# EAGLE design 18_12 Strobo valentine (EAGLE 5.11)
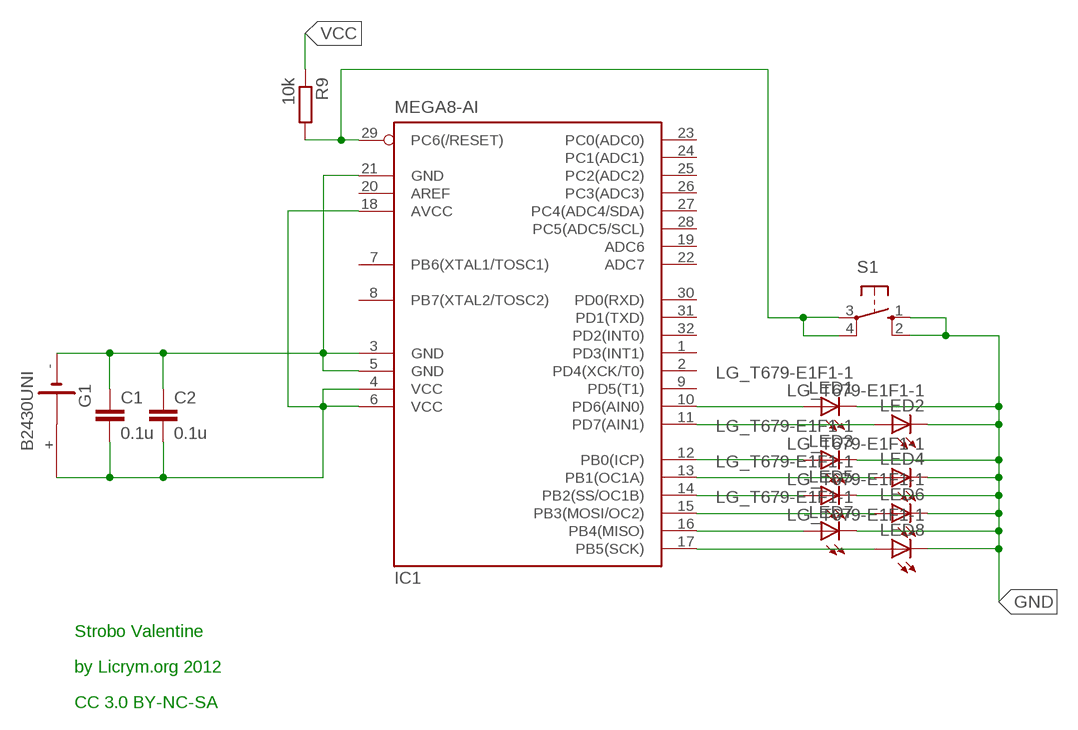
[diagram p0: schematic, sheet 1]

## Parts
C1  0.1u  C-EUC1206  [C1206]
C2  0.1u  C-EUC1206  [C1206]
G1  B2430UNI  [B2430UNI]
IC1  MEGA8-AI  [TQFP32-08]
LED1  LG_T679-E1F1-1  [PLCC2]
LED2  LG_T679-E1F1-1  [PLCC2]
LED3  LG_T679-E1F1-1  [PLCC2]
LED4  LG_T679-E1F1-1  [PLCC2]
LED5  LG_T679-E1F1-1  [PLCC2]
LED6  LG_T679-E1F1-1  [PLCC2]
LED7  LG_T679-E1F1-1  [PLCC2]
LED8  LG_T679-E1F1-1  [PLCC2]
R9  10k  R-EU_M1206  [M1206]
S1  10-XX  [B3F-10XX]

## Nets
GND: C1.1 C2.1 G1.- IC1.3(GND) IC1.5(GND) IC1.21(GND) LED1.C LED2.C LED3.C LED4.C LED5.C LED6.C LED7.C LED8.C S1.1(S) S1.2(S1)
N$3: IC1.29(PC6(/RESET)) R9.2 S1.3(P) S1.4(P1)
N$4: IC1.10(PD6(AIN0)) LED1.A
N$5: IC1.11(PD7(AIN1)) LED2.A
N$7: IC1.13(PB1(OC1A)) LED4.A
N$8: IC1.14(PB2(SS/OC1B)) LED5.A
N$9: IC1.15(PB3(MOSI/OC2)) LED6.A
N$10: IC1.16(PB4(MISO)) LED7.A
N$11: IC1.17(PB5(SCK)) LED8.A
N$14: IC1.12(PB0(ICP)) LED3.A
VCC: C1.2 C2.2 G1.+ IC1.4(VCC) IC1.6(VCC) IC1.18(AVCC) R9.1
Unconnected: G1.+@1(+) G1.+@2(+) G1.+@3(+) G1.+@4(+) G1.-@1(-) IC1.1(PD3(INT1)) IC1.2(PD4(XCK/T0)) IC1.7(PB6(XTAL1/TOSC1)) IC1.8(PB7(XTAL2/TOSC2)) IC1.9(PD5(T1)) IC1.19(ADC6) IC1.20(AREF) IC1.22(ADC7) IC1.23(PC0(ADC0)) IC1.24(PC1(ADC1)) IC1.25(PC2(ADC2)) IC1.26(PC3(ADC3)) IC1.27(PC4(ADC4/SDA)) IC1.28(PC5(ADC5/SCL)) IC1.30(PD0(RXD)) IC1.31(PD1(TXD)) IC1.32(PD2(INT0))

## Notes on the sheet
- Strobo Valentine
- by Licrym.org 2012
- CC 3.0 BY-NC-SA

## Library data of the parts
C1 C2 = rcl:C-EU: CAPACITOR, European symbol
G1 = battery:B2430UNI: LI BATTERY
IC1 = atmel:MEGA8: MICROCONTROLLER 8 Kbytes FLASH, 1 kbytes SRAM, 512 bytes EEPROM, USART, 6-channel 10 bit ADC, 2-channel 8 bit ADC Pin compatible with Atmega48, ATMega88, ATMega168 Source: avr.lbr; MPN: ATMEGA8-16AU; OC_FARNELL: 9171371; OC_NEWARK: 73M8863
LED1-LED8 = led:*_T679-?-1: LC TOPLED® Low Current LED; COLOR: green
R9 = rcl:R-EU_: RESISTOR, European symbol
S1 = switch-omron:10-XX: OMRON SWITCH; MPN: B3F-1000; OC_FARNELL: 176432; OC_NEWARK: 36M3542

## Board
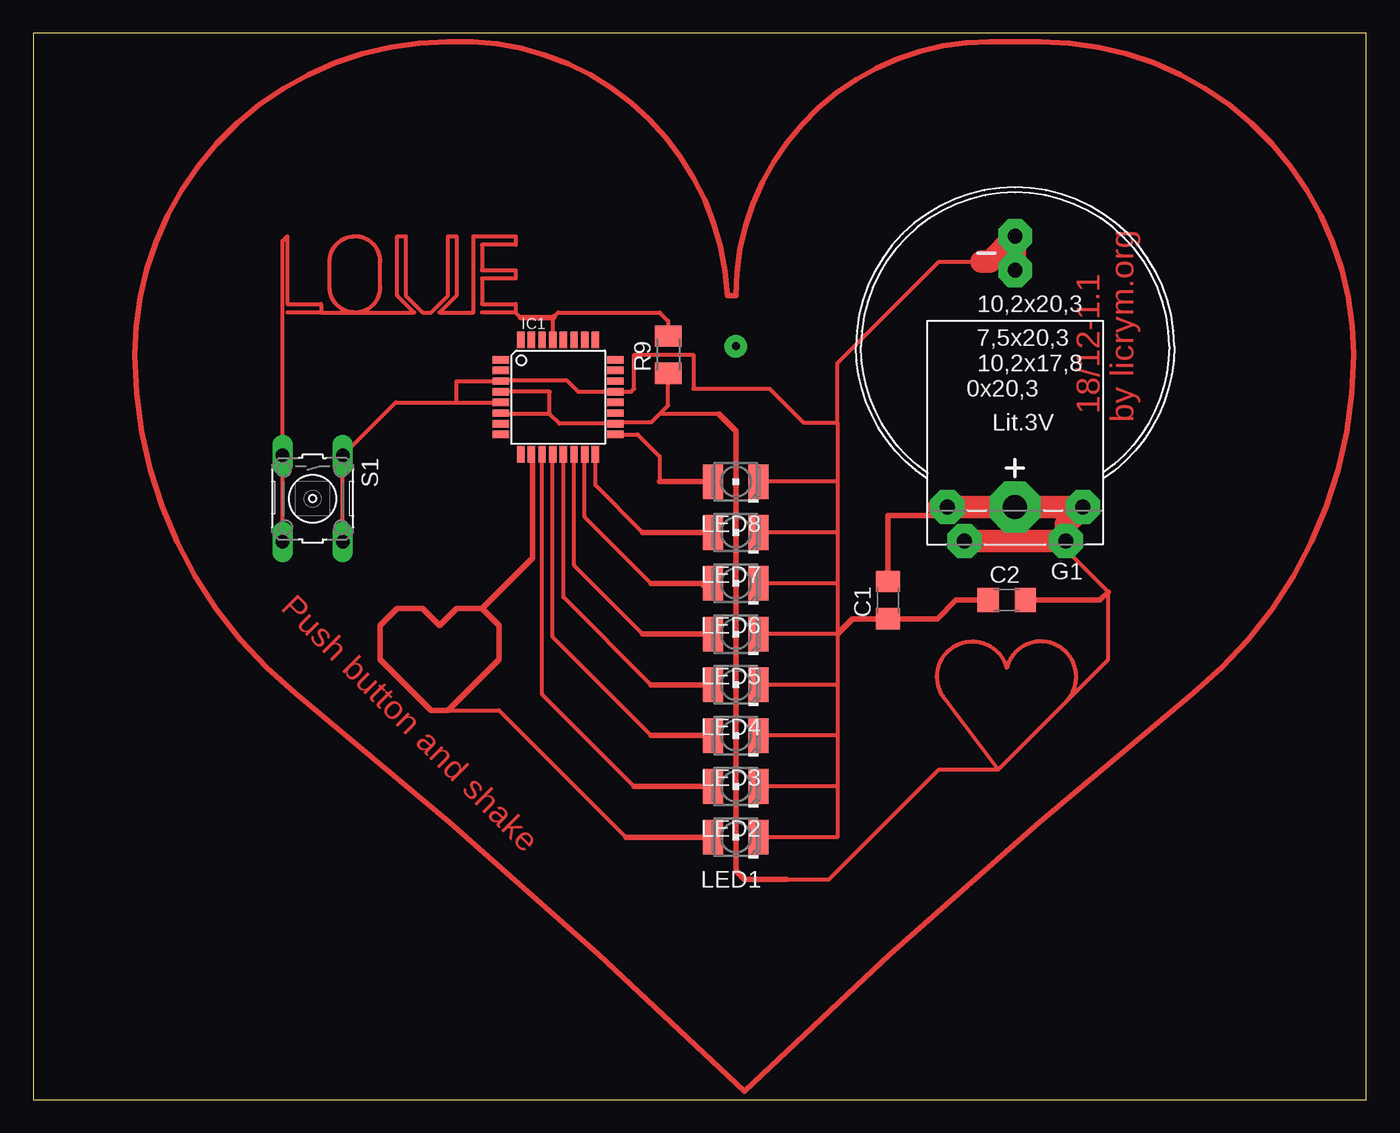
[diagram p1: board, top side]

Size 100 x 80 mm. Coordinates in mm from the lower left corner, seen from the top.
Outline: 0,0 100,0 100,80 0,80 0,0
Copper layers (1*16): Top 0.035mm / dielectric 1.5mm / Bottom 0.035mm
Design rules "default": minimum track width 10mil, minimum drill 24mil, track to track 8mil, track to pad 8mil, pad to pad 8mil, via to via 8mil, smd to smd 8mil, copper to edge 40mil, drill to drill 8mil, minimum pad ring 10mil, minimum via ring 8mil, stop-mask expansion 4mil, vias tented up to drill 0mil, thermal gap 10mil

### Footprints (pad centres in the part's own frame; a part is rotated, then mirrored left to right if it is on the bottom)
C1206 = smd 1.6 x 1.8: 1 -1.4,0; 2 1.4,0
B2430UNI = drill 1.118 pad 2.54 octagon: + 3.81,14.605; +@1 -3.81,14.605; +@2 -5.08,12.065; +@3 5.08,12.065; - 0,-5.715; -@1 0,-8.255 | drill 1.803 pad 3.81 octagon: +@4 0,12.065
TQFP32-08 = smd 1.27 x 0.559: 1 -4.293,2.8; 2 -4.293,2; 3 -4.293,1.2; 4 -4.293,0.4; 5 -4.293,-0.4; 6 -4.293,-1.2; 7 -4.293,-2; 8 -4.293,-2.8; 17 4.293,-2.8; 18 4.293,-2; 19 4.293,-1.2; 20 4.293,-0.4; 21 4.293,0.4; 22 4.293,1.2; 23 4.293,2; 24 4.293,2.8 | smd 0.559 x 1.27: 9 -2.8,-4.293; 10 -2,-4.293; 11 -1.2,-4.293; 12 -0.4,-4.293; 13 0.4,-4.293; 14 1.2,-4.293; 15 2,-4.293; 16 2.8,-4.293; 25 2.8,4.293; 26 2,4.293; 27 1.2,4.293; 28 0.4,4.293; 29 -0.4,4.293; 30 -1.2,4.293; 31 -2,4.293; 32 -2.8,4.293
PLCC2 = smd 2.6 x 1.5: A 0,1.7; C 0,-1.7
M1206 = smd 1.6 x 2: 1 -1.4,0; 2 1.4,0
B3F-10XX = drill 1.016 long: 1 -3.251,2.261; 2 3.251,2.261; 3 -3.251,-2.261; 4 3.251,-2.261

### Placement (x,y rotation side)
C1  64.14,37.47 90 top
C2  73.03,37.47 0 top
G1  73.66,56.52 180 top
IC1  39.37,52.7 0 top
LED1  52.7,19.68 90 top
LED2  52.7,23.5 90 top
LED3  52.7,27.3 90 top
LED4  52.7,31.11 90 top
LED5  52.7,34.92 90 top
LED6  52.7,38.73 90 top
LED7  52.7,42.55 90 top
LED8  52.7,46.35 90 top
R9  47.62,55.88 90 top
S1  20.95,45.09 270 top

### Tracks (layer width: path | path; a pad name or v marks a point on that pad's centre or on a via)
GND
  Top 0.305: S1.2 S1.1 27.18,52.3 31.75,52.3 | 31.75,52.3 IC1.5 | 31.75,52.3 31.75,53.91 IC1.3 35.15,53.98 40.01,53.98 40.88,53.1 IC1.21 44.85,53.1 45.09,53.34 45.09,55.88 49.53,55.88 49.53,53.34 55.24,53.34 57.78,50.8 60.33,50.8 | LED1.C 60.33,19.68 60.33,23.5 | 60.33,27.3 60.33,23.5 | 60.33,31.11 60.33,27.3 | 60.33,34.92 60.33,31.11 | 60.33,38.73 60.33,34.92 | 60.33,42.55 60.33,38.73 | 60.33,46.35 60.33,42.55 | 60.33,46.35 LED8.C | 60.33,42.55 LED7.C | 60.33,38.73 LED6.C | 60.33,34.92 LED5.C | 60.33,31.11 LED4.C | 60.33,27.3 LED3.C | 60.33,23.5 LED2.C | 60.33,50.8 60.33,46.35 | 60.33,50.8 60.33,55.24 67.94,62.87 71.12,62.87
  Top 0.406: 60.33,34.92 61.47,36.06 C1.1 67.81,36.06 69.22,37.47 C2.1
  Top 1.676: 71.12,62.87 71.75,62.87 73.66,64.77 G1.-
N$2
  Top 0.406: 31.11,79.38 arc90 7.62,55.88 arc51 19.68,30.48 arc-5 53.34,0.64
N$3
  Top 0.305: IC1.29 38.97,58.66 39.05,58.74 39.37,59.05 46.99,59.05 47.62,58.42 R9.2 | S1.4 S1.3 18.69,64.41 19.05,64.77 19.05,59.69 21.59,59.69 21.59,59.05 | 21.59,59.05 19.05,59.05 | 21.59,59.05 24.13,59.05 | 24.13,59.05 arc-90 22.23,60.96 22.23,62.87 arc-90 24.13,64.77 arc-90 26.04,62.87 26.04,60.96 arc-90 24.13,59.05 | 24.13,59.05 28.57,59.05 27.3,60.33 27.3,64.77 27.94,64.77 27.94,60.33 29.21,59.05 29.84,59.05 31.11,60.33 31.11,64.77 31.75,64.77 31.75,60.33 30.48,59.05 33.02,59.05 33.02,64.77 36.2,64.77 36.2,64.14 33.66,64.14 33.66,62.23 36.2,62.23 36.2,61.59 33.66,61.59 33.66,59.69 36.2,59.69 36.2,59.05 | 36.2,59.05 33.66,59.05 | 36.2,59.05 36.57,58.68
  Top 0.406: 36.57,58.68 38.99,58.68 39.05,58.74
N$4
  Top 0.305: 44.45,19.68 34.92,29.21 31.11,29.21 | 37.47,48.32 IC1.10
  Top 0.406: 33.66,36.83 31.75,36.83 30.48,35.56 29.21,36.83 27.3,36.83 26.04,35.56 26.04,33.02 29.84,29.21 31.11,29.21 34.92,33.02 34.92,35.56 33.66,36.83 | 37.47,48.32 37.47,40.64 33.66,36.83 | 44.45,19.68 LED1.A
N$5
  Top 0.305: IC1.11 38.17,30.41 45.09,23.5
  Top 0.406: 45.09,23.5 LED2.A
N$7
  Top 0.305: IC1.13 39.77,37.7 46.35,31.11
  Top 0.406: 46.35,31.11 LED4.A
N$8
  Top 0.305: IC1.14 40.57,40.08 45.72,34.92
  Top 0.406: 45.72,34.92 LED5.A
N$9
  Top 0.305: IC1.15 41.37,43.72 46.35,38.73
  Top 0.406: 46.35,38.73 50.16,38.73 50.8,38.1 50.8,38.53 LED6.A
N$10
  Top 0.305: IC1.16 42.17,46.09 45.72,42.55
  Top 0.406: 45.72,42.55 LED7.A
N$11
  Top 0.305: IC1.17 45.34,49.91 46.99,48.26 46.99,46.35
  Top 0.406: 46.99,46.35 LED8.A
N$14
  Top 0.305: IC1.12 38.97,34.69 46.35,27.3
  Top 0.406: 46.35,27.3 LED3.A
N$21  (via drill 0.6 pad 1.68)
  other vias: 52.7,56.52
N$24
  Top 0.406: 53.34,0.64 arc-5 87,30.48 arc51 99.06,55.88 arc90 75.56,79.38 71.75,79.38 arc90 52.7,60.33 52.07,60.33 arc90 31.11,79.38
VCC
  Top 0.305: IC1.6 35.15,51.44 38.73,51.44 | 38.73,51.44 39.47,50.7 IC1.18 43.76,50.8 46.35,50.8 46.99,51.44 | IC1.4 38.73,53.1 38.73,51.44 | 56.52,16.51 59.69,16.51 67.94,24.77 72.39,24.77 77.47,29.84 | 51.44,51.44 46.99,51.44 | R9.1 47.62,52.07 46.99,51.44 | 77.47,29.84 arc211 73.03,32.38 | 77.47,29.84 80.64,33.02 80.64,38.1 76.83,41.91 71.75,41.91
  Top 0.406: C1.2 64.14,43.81 67.94,43.81 68.58,44.45 | C2.2 80.01,37.47 80.64,38.1 | 56.52,16.51 53.34,16.51 52.7,17.14 52.7,50.16 51.44,51.44
  Top 1.676: G1.+ 71.75,41.91 77.47,41.91 77.47,43.18 78.74,44.45 68.58,44.45 67.94,44.45
VCC1
  Top 0.305: 72.39,24.77 68.58,29.84 arc-211 73.03,32.38

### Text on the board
Top: 18/12-1.1 | by licrym.org | Push button and shake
